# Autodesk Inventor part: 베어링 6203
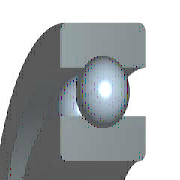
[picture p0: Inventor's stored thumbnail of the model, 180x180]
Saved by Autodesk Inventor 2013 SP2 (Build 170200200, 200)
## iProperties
IsCustomPart: 0
Company: 한국ATC센터
Created: 2014-10
Part Number: 베어링 6203
Material: Steel, Mild
Description: 깊은 그루브 볼 베어링
Document SubType Name: Modeling
Standard: KS B 2023
Designer: KYOUNG IL JANG
Standards Organization: KS
Language: ko-KR
Size Designation: 6203 - 17 x 40 x 12
Categories: <MemberInstance><Categories><Category DisplayName="샤프트 부품" InternalName="7f7aeb1f-a693-4053-b835-cee3144e0d98" Mnemonic="SHFT"><Category DisplayName="베어링" Inter
Density: 7.86 g/cm^3
Mass: 64.9809 g
Surface Area: 64.3582 cm^2
Volume: 8.26729 cm^3
Author: KYOUNG IL JANG
Revision Number: 1
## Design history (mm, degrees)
sketch "스케치" dims "d0" = 5.98 (= -0.26 x WD + 0.26 x BD)
  geometry: L1 (3.01, 14.25)-(8.99, 14.25); L2 (6, 14.25)-(6, 11.26); L3 (6, 14.25)-(6, 17.24); L4 (3.778, 12.249)-(0, 12.249); L5 (0, 8.5)-(12, 8.5); L6 (3.778, 16.251)-(0, 16.251); L7 (0, 20)-(12, 20); L8 (12, 8.5)-(12, 12.249); L9 (8.222, 12.249)-(12, 12.249); L10 (8.222, 16.251)-(12, 16.251); L11 (12, 20)-(12, 16.251); L12 (-1.4, 0)-(8.4, 0) reference; L13 (0, -0.3)-(0, 5.3) reference
  constraints: 22 end point, 4 point on line, 2 collinear, 2 perpendicular, 2 symmetric about line, 1 midpoint, 1 parallel, 14 other
  dimensions: "d9" = 17 diameter of L5 L12 (= WD); "d11" = 40 diameter of L7 L12 (= BD); "d12" = 12 distance between parallel lines of L8 L13 (= KB); "d13" = 24.498 diameter of L9 L12 (= 0.326 x BD + 0.674 x WD)
revolve "본체" stored, may be unused: angle "d6" = 90 deg
revolve "볼" stored, may be unused: angle "d7" = 90 deg
pattern_circular "IDS_ARRAYBALL[SIMPL:T]" dims angle "d3" = 360 deg
body "Solid1"
fillet "모깎기1" dims "d1" = 0.6 (= KRS)
other parameters: "WD" = 17 [user parameter; used in 5 equation terms], "BD" = 40 [user parameter; used in 5 equation terms], "KB" = 12 [user parameter; used in 1 equation term], "KRS" = 0.6 [user parameter; used in 1 equation term], "d4" = 0, "d5" = 0, "d8" = 0, "d14" = 0, "d15" = 0, "BBA" = 0 [user parameter], "BC0" = 4750000 [user parameter], "BC" = 9560000 [user parameter], "WR" = 8.5 (= 0.5 x WD) [user parameter]
